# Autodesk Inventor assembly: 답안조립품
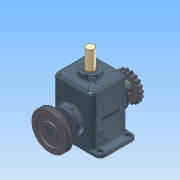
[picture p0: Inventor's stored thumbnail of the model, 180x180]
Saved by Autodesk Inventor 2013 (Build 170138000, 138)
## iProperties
Created: 2015-03
Part Number: 답안조립품
Document SubType Name: Assembly
Designer: Administrator
Mass: 8579 g
Surface Area: 4386.44 cm^2
Volume: 1982.5 cm^3
Density: 4.32736 g/cm^3
Author: Administrator
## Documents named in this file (15)
- C:\Documents and Settings\Administrator\바탕 화면\350305V1022\답안조립품.iam
- C:\Documents and Settings\Administrator\바탕 화면\350305V1022\본체.ipt
- C:\Documents and Settings\Administrator\바탕 화면\350305V1022\M4x0.5.ipt
- C:\Documents and Settings\Administrator\바탕 화면\350305V1022\베어링 6205.ipt
- C:\Documents and Settings\Administrator\바탕 화면\350305V1022\오일실.ipt
- C:\Documents and Settings\Administrator\바탕 화면\350305V1022\커버.ipt
- C:\Documents and Settings\Administrator\바탕 화면\350305V1022\편심축.ipt
- C:\Documents and Settings\Administrator\바탕 화면\350305V1022\멈춤링.ipt
- C:\Documents and Settings\Administrator\바탕 화면\350305V1022\멈춤나사 M5x0.5.ipt
- C:\Documents and Settings\Administrator\바탕 화면\350305V1022\체인 스프로킷.ipt
- C:\Documents and Settings\Administrator\바탕 화면\350305V1022\키 8x8.ipt
- C:\Documents and Settings\Administrator\바탕 화면\350305V1022\V-벨트풀리.ipt
- C:\Documents and Settings\Administrator\바탕 화면\350305V1022\슬라이드.ipt
- C:\Documents and Settings\Administrator\바탕 화면\350305V1022\부시.ipt
- C:\Documents and Settings\Administrator\바탕 화면\350305V1022\7 - 가변스프링.ipt
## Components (9 placed, 4 different names)
1. 5-체인 스프로킷:1 — 플러쉬:2, 각도:2
2. V-벨트풀리:1 — 플러쉬:3, 각도:4
3. 7 - 가변스프링:1
4. M4x0.5:1
5. M4x0.5:2
6. M4x0.5:3
7. M4x0.5:4
8. M4x0.5:5
9. M4x0.5:6
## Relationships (4: Flush 2, Angle 2)
- 플러쉬:2 [Flush]: 5-체인 스프로킷:1
- 각도:2 [Angle]: 5-체인 스프로킷:1
- 플러쉬:3 [Flush]: V-벨트풀리:1
- 각도:4 [Angle]: V-벨트풀리:1
